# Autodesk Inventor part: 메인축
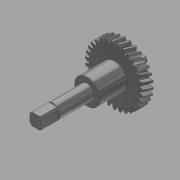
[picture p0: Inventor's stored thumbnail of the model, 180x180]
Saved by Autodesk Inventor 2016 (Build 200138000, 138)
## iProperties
Created: 2017-11
Part Number: 메인축
Material: 강철, 탄소
Document SubType Name: Modeling
Designer: mduedu
Categories: <?xml version="1.0" encoding="UTF-16"?> <MemberInstance><Categories><FamilyTemplate><FamilyTemplateParameter ValueType="xs:double" Id="1" ObjectReferenceKey="da
Density: 7.87 g/cm^3
Mass: 607.365 g
Surface Area: 183.17 cm^2
Volume: 77.1747 cm^3
Appearance: 반광택
CustomPartVersion: 1
Author: mduedu
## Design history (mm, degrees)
sketch "Sketch1"
  geometry: C1 r 34.094 at (0, 0)
  constraints: 1 centre point
  dimensions: "d0" = 68.18712 diameter of C1 (= da_da)
extrude "Extrusion1" new body sketch "Sketch1" distance "d1" = 12 (= da_b); taper "d2" = 0 deg
workplane "Work Plane2"
sketch "Sketch2"
  geometry: C1 r 34.094 at (0, 0) reference; C2 r 32.094 at (0, 0)
  constraints: 1 centre point, 1 coincident
  dimensions: "d3" = 64.18712 diameter of C2 (= da_dw)
feature "피치 지름" sketch "Sketch2" dims "d4" = 10, "d5" = 0
workplane "Work Plane8"
workplane "Work Plane9"
feature "스퍼 기어" dims "d34" = 1.01342 (computed from da_z), "da_b" = 12, "da_d" = 64.18712, "da_aw" = 54.86964, "da_da" = 68.18712, "da_df" = 59.18712, "da_dw" = 64.18712, angle "da_beta" = 15 deg, "da_lefttooth" = 0, "da_righttooth" = 10
sketch "스케치3"
  geometry: C1 r 15 at (0, 0); 1 further point
  constraints: 1 centre point, 1 coincident
  dimensions: "d49" = 30 diameter of C1
extrude "돌출2" join sketch "스케치3" distance "d50" = 32; taper "d51" = 0 deg
sketch "스케치4"
  geometry: C1 r 8.5 at (0, 0); 1 further point
  constraints: 1 centre point, 1 coincident
  dimensions: "d52" = 17 diameter of C1
extrude "돌출3" join sketch "스케치4" distance "d53" = 60; taper "d54" = 0 deg
sketch "스케치5"
  geometry: C1 r 7.5 at (0, 0); 1 further point
  constraints: 1 centre point, 1 coincident
  dimensions: "d55" = 15 diameter of C1
extrude "돌출4" join sketch "스케치5" distance "d56" = 16; taper "d57" = 0 deg
sketch "스케치6"
  geometry: C1 r 4 at (0, 0); 1 further point
  constraints: 1 centre point, 1 coincident
  dimensions: "d58" = 8 diameter of C1
extrude "돌출5" join sketch "스케치6" distance "d59" = 7; taper "d60" = 0 deg
chamfer "모따기1" distance "d61" = 0.5; stored, may be unused: second distance "d62" = 2, angle "d63" = 45 deg
fillet "모깎기1" dims "d64" = 0.5
sketch "스케치7"
  geometry: L1 (-7, -7)-(7, -7); L2 (7, -7)-(7, 7); L3 (7, 7)-(-7, 7); L4 (-7, 7)-(-7, -7); L5 (-7, -7)-(7, 7); L6 (7, -7)-(-7, 7); L7 (-10, -10)-(10, -10); L8 (10, -10)-(10, 10); L9 (10, 10)-(-10, 10); L10 (-10, 10)-(-10, -10); L11 (-10, -10)-(10, 10); L12 (10, -10)-(-10, 10); 1 further point
  constraints: 24 end point, 4 midpoint, 4 parallel, 2 horizontal, 2 perpendicular
  dimensions: "d65" = 14 distance of L3.end L2.end; "d66" = 14 distance of L2.end L1.end; "d67" = 20 distance of L9.end L8.end; "d68" = 20 distance of L8.end L7.end
extrude "돌출6" cut sketch "스케치7" distance "d69" = 20; taper "d70" = 0 deg
body "Solid1"
body "Srf1"
other parameters: "d16" = 54.86964 (= da_aw), "d17" = 0, "d39" = 0, "d41" = 0, "d43" = 54.86964 (= da_aw), "d46" = 54.86964 (= da_aw), "d47" = 0, "d48" = 0
